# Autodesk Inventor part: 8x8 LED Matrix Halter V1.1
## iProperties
Created: 2016-11
Part Number: 8x8 LED Matrix Halter V1.1
Material: Standard
Document SubType Name: Blech
Designer: Acer
Density: 1 g/cm^3
Sheet Metal Rule: Standard_mm
Author: Acer
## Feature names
1. Extrusion1
2. Extrusion2
3. Extrusion3
